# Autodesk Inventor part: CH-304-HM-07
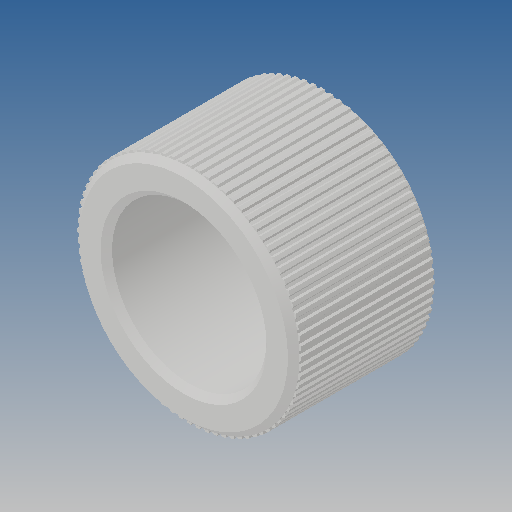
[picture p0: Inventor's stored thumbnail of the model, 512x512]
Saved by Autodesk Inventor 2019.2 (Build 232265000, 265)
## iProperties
Created: 2015-08
Part Number: CH-304-HM-07
Material: Ogólny
Document SubType Name: Modeling
Designer: CADENGINEERING4
Density: 1 g/cm^3
Appearance: Domyślna
Author: CADENGINEERING4
Revision Number: ÈÎºÎ
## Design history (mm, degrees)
feature "ÕóÁÐ(Ô²ÖÜ)1"
node "Bryła1"
